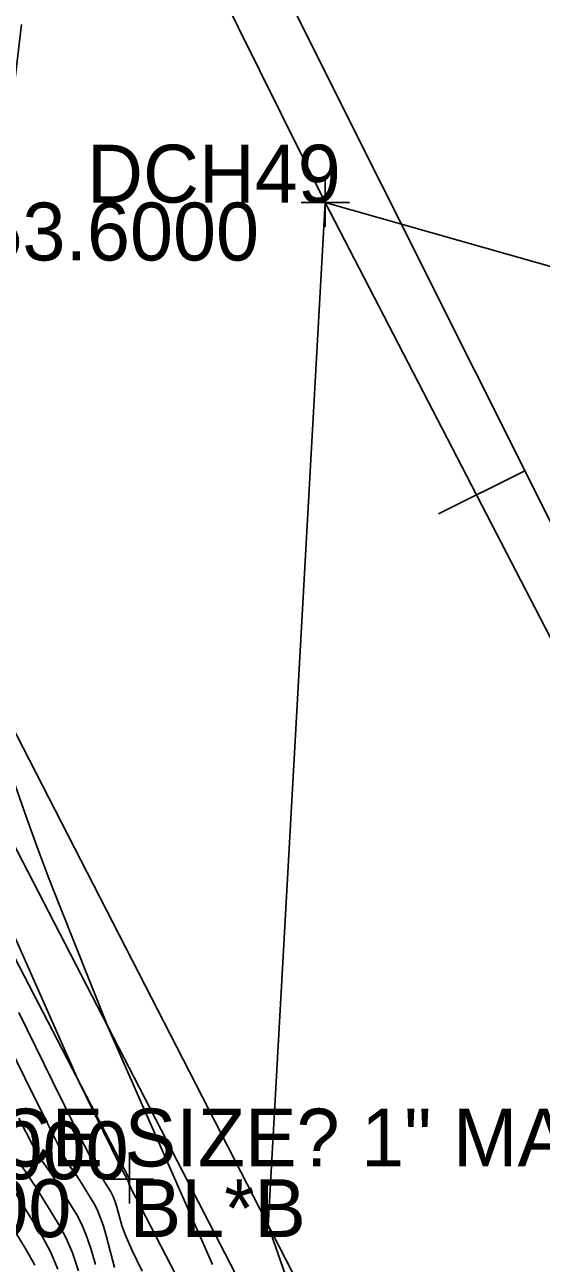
# Model space of a CAD drawing. Extents: x 1654928 to 1810050, y 486881 to 626330.
# Drawn here: x 1801417.31 to 1801428.02, y 489814.52 to 489840.21 of the extents above; entities that cross this region are included whole.
import ezdxf

# ---------------------------------------------------------------- set-up
doc = ezdxf.new("R2010")
doc.units = 0
for name, color, linetype in [('DT_X_Contour_Major', 7, 'Continuous'), ('DT_X_Contour_Minor', 7, 'Continuous'), ('PV_X_EOP', 7, 'Continuous'), ('PV_X_Shoulder', 7, 'Continuous'), ('SV_X_Break_Lines', 7, 'Continuous'), ('SV_X_Center_of_Pavt', 7, 'Continuous'), ('SV_X_CL_Survey_20', 7, 'Continuous'), ('SV_X_Shot_Marker', 7, 'Continuous'), ('SV_X_Text_Comment', 7, 'Continuous'), ('SV_X_Text_Elevation', 7, 'Continuous'), ('SV_X_Text_Name', 7, 'Continuous')]:
    doc.layers.add(name, color=color, linetype=linetype)

msp = doc.modelspace()

# ---------------------------------------------------------------- linework, layer by layer
at = {"layer": 'DT_X_Contour_Major'}
for points in [[(1801417.18, 489819.721), (1801417.881, 489818.3), (1801418.388, 489817.277), (1801418.701, 489816.65), (1801418.82, 489816.42), (1801418.88, 489816.336), (1801418.904, 489816.301), (1801418.932, 489816.26), (1801418.962, 489816.212), (1801418.996, 489816.157), (1801419.091, 489816.003), (1801419.126, 489815.937), (1801419.161, 489815.854), (1801419.195, 489815.754), (1801419.228, 489815.638), (1801419.317, 489815.304), (1801419.386, 489815.116), (1801419.527, 489814.802), (1801419.739, 489814.361)], [(1801416.802, 489815.672), (1801417.327, 489814.817), (1801417.514, 489814.482)]]:
    msp.add_lwpolyline(points, dxfattribs=at)
at = {"layer": 'DT_X_Contour_Minor'}
for points in [[(1801417.236, 489840.216), (1801417.068, 489838.815), (1801416.563, 489834.932), (1801416.393, 489833.578), (1801416.261, 489832.429), (1801416.168, 489831.486), (1801416.113, 489830.747), (1801415.947, 489827.777), (1801417.104, 489824.439), (1801417.348, 489823.746), (1801417.583, 489823.097), (1801417.811, 489822.491), (1801418.03, 489821.93), (1801419.035, 489819.412), (1801421.198, 489814.495)], [(1801437.81, 489832.47), (1801423.54, 489836.522), (1801422.354, 489815.308), (1801422.713, 489814.272), (1801422.814, 489813.994), (1801422.962, 489813.604), (1801423.159, 489813.1), (1801423.403, 489812.485), (1801424.118, 489810.693), (1801424.371, 489810.056), (1801424.595, 489809.489), (1801424.79, 489808.992), (1801424.955, 489808.565), (1801425.357, 489807.52), (1801425.498, 489807.155), (1801425.619, 489806.844), (1801425.721, 489806.587), (1801425.804, 489806.385), (1801426.144, 489805.566), (1801431.518, 489793.935)], [(1801414.941, 489826.147), (1801418.411, 489818.322), (1801419.114, 489816.895), (1801419.246, 489816.628), (1801419.341, 489816.435), (1801419.419, 489816.278), (1801419.424, 489816.271), (1801419.427, 489816.267), (1801419.429, 489816.264), (1801419.432, 489816.259), (1801419.447, 489816.234), (1801419.45, 489816.227), (1801419.453, 489816.218), (1801419.456, 489816.207), (1801419.464, 489816.177), (1801419.483, 489816.131), (1801419.503, 489816.091), (1801419.528, 489816.039), (1801419.606, 489815.887), (1801420.23, 489814.684), (1801420.676, 489813.825)], [(1801416.651, 489819.694), (1801417.306, 489818.368), (1801417.786, 489817.404), (1801418.091, 489816.802), (1801418.221, 489816.561), (1801418.336, 489816.401), (1801418.382, 489816.335), (1801418.434, 489816.256), (1801418.493, 489816.165), (1801418.557, 489816.06), (1801418.738, 489815.766), (1801418.805, 489815.64), (1801418.871, 489815.481), (1801418.936, 489815.291), (1801419, 489815.068), (1801419.17, 489814.432)], [(1801417.184, 489817.532), (1801417.481, 489816.954), (1801417.622, 489816.703), (1801417.791, 489816.467), (1801417.859, 489816.369), (1801417.937, 489816.252), (1801418.023, 489816.117), (1801418.118, 489815.963), (1801418.385, 489815.529), (1801418.484, 489815.342), (1801418.582, 489815.108), (1801418.678, 489814.827), (1801418.773, 489814.498)], [(1801416.335, 489817.136), (1801416.425, 489816.986), (1801416.703, 489816.597), (1801416.815, 489816.436), (1801416.942, 489816.245), (1801417.084, 489816.022), (1801417.241, 489815.769), (1801417.68, 489815.054), (1801417.84, 489814.756), (1801417.994, 489814.399)], [(1801417.247, 489816.532), (1801417.337, 489816.402), (1801417.439, 489816.248), (1801417.553, 489816.07), (1801417.679, 489815.866), (1801418.032, 489815.292), (1801418.164, 489815.045), (1801418.293, 489814.735), (1801418.42, 489814.363)]]:
    msp.add_lwpolyline(points, dxfattribs=at)
at = {"layer": 'PV_X_EOP'}
msp.add_lwpolyline([(1801513.785, 489634.043), (1801503.26, 489654.965), (1801492.692, 489675.84), (1801481.803, 489697.704), (1801472.078, 489717.629), (1801460.782, 489739.414), (1801448.005, 489764.97), (1801436.553, 489786.89), (1801425.237, 489809.697), (1801414.345, 489830.894), (1801402.21, 489854.742), (1801391.781, 489876.056), (1801380.008, 489899.32), (1801369.395, 489920.807), (1801356.62, 489946.308), (1801346.845, 489965.404), (1801335.257, 489988.444)], dxfattribs=at)
at = {"layer": 'PV_X_Shoulder'}
msp.add_lwpolyline([(1801513.053, 489633.484), (1801502.425, 489654.401), (1801492.155, 489675.438), (1801481.048, 489697.245), (1801471.095, 489717.056), (1801459.974, 489738.844), (1801446.996, 489764.517), (1801435.938, 489786.184), (1801424.33, 489809.156), (1801413.386, 489830.353), (1801401.606, 489854.259), (1801390.811, 489875.349), (1801379.301, 489898.985), (1801368.607, 489920.204), (1801355.561, 489945.921), (1801346.174, 489964.922), (1801334.144, 489988.199)], dxfattribs=at)
at = {"layer": 'SV_X_Break_Lines'}
msp.add_lwpolyline([(1801419.479, 489816.264), (1801413.606, 489827.582), (1801399.229, 489854.903), (1801388.205, 489875.792), (1801377.391, 489897.446), (1801365.991, 489920.501), (1801353.319, 489946.375), (1801342.526, 489967.898), (1801332.595, 489987.823)], dxfattribs=at)
at = {"layer": 'SV_X_Center_of_Pavt'}
msp.add_lwpolyline([(1801523.585, 489638.313), (1801512.853, 489659.481), (1801502.374, 489680.412), (1801490.819, 489703.952), (1801481.428, 489721.68), (1801470.803, 489742.834), (1801457.335, 489769.613), (1801446.389, 489792.464), (1801435.307, 489813.792), (1801423.54, 489836.522), (1801412.234, 489859.298), (1801401.202, 489881.345), (1801390.005, 489903.67), (1801378.784, 489926.715), (1801366.669, 489950.371), (1801356.567, 489970.63), (1801345.517, 489992.708)], dxfattribs=at)
at = {"layer": 'SV_X_CL_Survey_20'}
for p, q in [((1802886.975, 486913.246), (1801128.538, 490429.055)), ((1802886.975, 486913.246), (1801128.538, 490429.055)), ((1801427.676, 489830.959), (1801425.888, 489830.064))]:
    msp.add_line(p, q, dxfattribs=at)
at = {"layer": 'SV_X_Shot_Marker'}
for p, q in [((1801423.54, 489837.022), (1801423.54, 489836.022)), ((1801423.04, 489836.522), (1801424.04, 489836.522)), ((1801423.54, 489836.522), (1801423.54, 489836.522)), ((1801419.479, 489816.764), (1801419.479, 489815.764)), ((1801418.979, 489816.264), (1801419.979, 489816.264)), ((1801419.479, 489816.264), (1801419.479, 489816.264))]:
    msp.add_line(p, q, dxfattribs=at)

# ---------------------------------------------------------------- texts
at = {"layer": 'SV_X_Text_Comment'}
for s, p in [('USE? FENCE SIZE? 1" MAT? STEEL', (1801408.855, 489816.529)), ('BL*B', (1801419.479, 489815.064))]:
    msp.add_text(s, height=1.2, dxfattribs=at).set_placement(p)
at = {"layer": 'SV_X_Text_Elevation'}
for s, p in [('853.6000', (1801415.472, 489835.322)), ('853.2200', (1801411.58, 489815.064))]:
    msp.add_text(s, height=1.2, dxfattribs=at).set_placement(p)
at = {"layer": 'SV_X_Text_Name'}
for s, p in [('DCH49', (1801418.599, 489836.522)), ('JMR1000', (1801412.592, 489816.264))]:
    msp.add_text(s, height=1.2, dxfattribs=at).set_placement(p)

doc.saveas('drawing.dxf')
